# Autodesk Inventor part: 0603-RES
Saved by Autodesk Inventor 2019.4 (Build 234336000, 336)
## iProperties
Created: 2021-02
Part Number: 0603-RES
Material: Generic
Document SubType Name: Modeling
Designer: Administrator
Density: 1 g/cm^3
Appearance: Default
Title: 0603-RES
Author: Administrator
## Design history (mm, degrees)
feature "Body1"
body "Solid1"
